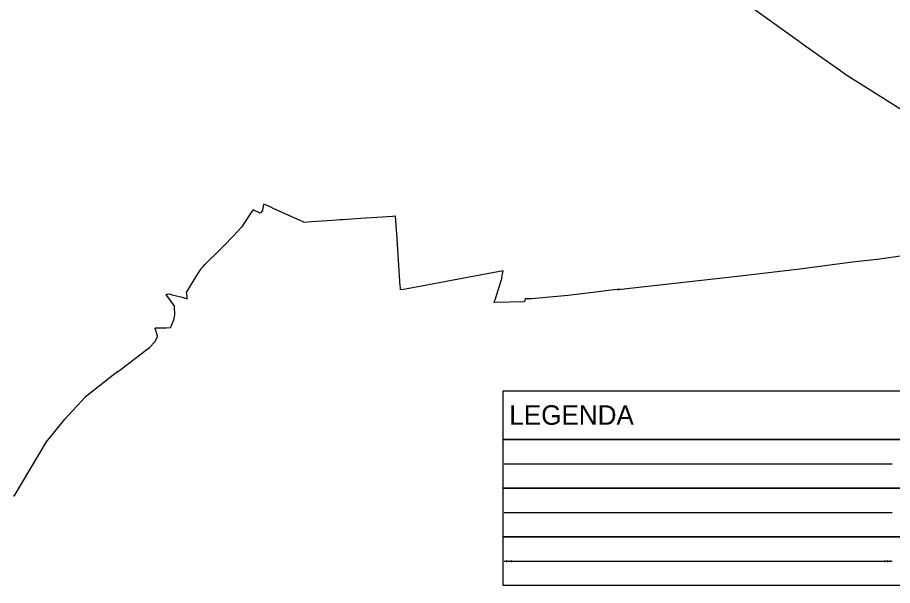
# Model space of a CAD drawing. Extents: x -601601 to -598591, y -1094361 to -1093021.
# Drawn here: x -600260 to -599362, y -1094361 to -1093778 of the extents above; entities that cross this region are included whole.
import ezdxf

# ---------------------------------------------------------------- set-up
doc = ezdxf.new("R2010")
doc.units = 0
for name, color, linetype in [('LEGENDA', 7, 'Continuous'), ('OVNE_PRE', 7, 'Continuous'), ('OVNE_SET', 7, 'Continuous')]:
    doc.layers.add(name, color=color, linetype=linetype)

msp = doc.modelspace()

# ---------------------------------------------------------------- linework, layer by layer
at = {"layer": 'LEGENDA'}
for p, q in [((-599760.54, -1094235.95), (-599362.54, -1094235.95)), ((-599760.54, -1094285.95), (-599362.54, -1094285.95)), ((-599760.54, -1094335.95), (-599362.54, -1094335.95))]:
    msp.add_line(p, q, dxfattribs=at)
for points in [[(-599761.54, -1094160.95), (-598861.54, -1094160.95), (-598861.54, -1094210.95), (-599761.54, -1094210.95), (-599761.54, -1094160.95)], [(-599761.54, -1094210.95), (-599361.54, -1094210.95), (-598861.54, -1094210.95), (-598861.54, -1094260.95), (-599361.54, -1094260.95), (-599761.54, -1094260.95), (-599761.54, -1094210.95)], [(-599761.54, -1094260.95), (-599361.54, -1094260.95), (-598861.54, -1094260.95), (-598861.54, -1094310.95), (-599361.54, -1094310.95), (-599761.54, -1094310.95), (-599761.54, -1094260.95)], [(-599761.54, -1094310.95), (-599361.54, -1094310.95), (-598861.54, -1094310.95), (-598861.54, -1094360.95), (-599361.54, -1094360.95), (-599761.54, -1094360.95), (-599761.54, -1094310.95)], [(-599758.21, -1094335.63), (-599758.02, -1094335.82), (-599758.02, -1094336.09), (-599758.21, -1094336.28), (-599758.48, -1094336.28), (-599758.67, -1094336.09), (-599758.67, -1094335.82), (-599758.48, -1094335.63), (-599758.21, -1094335.63), (-599758.2, -1094335.67), (-599758.44, -1094335.67), (-599758.52, -1094335.75), (-599758.12, -1094335.75), (-599758.06, -1094335.83), (-599758.6, -1094335.83), (-599758.6, -1094335.91), (-599758.07, -1094335.91), (-599758.06, -1094335.99), (-599758.59, -1094335.99), (-599758.59, -1094336.07), (-599758.06, -1094336.07), (-599758.11, -1094336.15), (-599758.54, -1094336.15), (-599758.47, -1094336.23), (-599758.19, -1094336.23)], [(-599755.7, -1094335.63), (-599755.51, -1094335.82), (-599755.51, -1094336.09), (-599755.7, -1094336.28), (-599755.97, -1094336.28), (-599756.16, -1094336.09), (-599756.16, -1094335.82), (-599755.97, -1094335.63), (-599755.7, -1094335.63), (-599755.71, -1094335.67), (-599755.95, -1094335.67), (-599756.03, -1094335.75), (-599755.63, -1094335.75), (-599755.55, -1094335.83), (-599756.11, -1094335.83), (-599756.11, -1094335.91), (-599755.55, -1094335.91), (-599755.55, -1094335.99), (-599756.11, -1094335.99), (-599756.11, -1094336.07), (-599755.55, -1094336.07), (-599755.63, -1094336.15), (-599756.03, -1094336.15), (-599755.95, -1094336.23), (-599755.71, -1094336.23)], [(-599753.19, -1094335.63), (-599753, -1094335.82), (-599753, -1094336.09), (-599753.19, -1094336.28), (-599753.46, -1094336.28), (-599753.65, -1094336.09), (-599753.65, -1094335.82), (-599753.46, -1094335.63), (-599753.19, -1094335.63), (-599753.23, -1094335.67), (-599753.47, -1094335.67), (-599753.53, -1094335.75), (-599753.15, -1094335.75), (-599753.07, -1094335.83), (-599753.59, -1094335.83), (-599753.59, -1094335.91), (-599753.07, -1094335.91), (-599753.07, -1094335.99), (-599753.59, -1094335.99), (-599753.6, -1094336.07), (-599753.08, -1094336.07), (-599753.12, -1094336.15), (-599753.53, -1094336.15), (-599753.48, -1094336.23), (-599753.24, -1094336.23)], [(-599369.61, -1094335.63), (-599369.42, -1094335.82), (-599369.42, -1094336.09), (-599369.61, -1094336.28), (-599369.88, -1094336.28), (-599370.07, -1094336.09), (-599370.07, -1094335.82), (-599369.88, -1094335.63), (-599369.61, -1094335.63), (-599369.6, -1094335.67), (-599369.84, -1094335.67), (-599369.92, -1094335.75), (-599369.52, -1094335.75), (-599369.46, -1094335.83), (-599370, -1094335.83), (-599370, -1094335.91), (-599369.47, -1094335.91), (-599369.46, -1094335.99), (-599369.99, -1094335.99), (-599369.99, -1094336.07), (-599369.46, -1094336.07), (-599369.51, -1094336.15), (-599369.94, -1094336.15), (-599369.87, -1094336.23), (-599369.59, -1094336.23)], [(-599367.1, -1094335.63), (-599366.91, -1094335.82), (-599366.91, -1094336.09), (-599367.1, -1094336.28), (-599367.37, -1094336.28), (-599367.56, -1094336.09), (-599367.56, -1094335.82), (-599367.37, -1094335.63), (-599367.1, -1094335.63), (-599367.11, -1094335.67), (-599367.35, -1094335.67), (-599367.43, -1094335.75), (-599367.03, -1094335.75), (-599366.95, -1094335.83), (-599367.51, -1094335.83), (-599367.51, -1094335.91), (-599366.95, -1094335.91), (-599366.95, -1094335.99), (-599367.51, -1094335.99), (-599367.51, -1094336.07), (-599366.95, -1094336.07), (-599367.03, -1094336.15), (-599367.43, -1094336.15), (-599367.35, -1094336.23), (-599367.11, -1094336.23)], [(-599364.59, -1094335.63), (-599364.4, -1094335.82), (-599364.4, -1094336.09), (-599364.59, -1094336.28), (-599364.86, -1094336.28), (-599365.05, -1094336.09), (-599365.05, -1094335.82), (-599364.86, -1094335.63), (-599364.59, -1094335.63), (-599364.63, -1094335.67), (-599364.87, -1094335.67), (-599364.93, -1094335.75), (-599364.55, -1094335.75), (-599364.47, -1094335.83), (-599364.99, -1094335.83), (-599364.99, -1094335.91), (-599364.47, -1094335.91), (-599364.47, -1094335.99), (-599364.99, -1094335.99), (-599365, -1094336.07), (-599364.48, -1094336.07), (-599364.52, -1094336.15), (-599364.93, -1094336.15), (-599364.88, -1094336.23), (-599364.64, -1094336.23)]]:
    msp.add_lwpolyline(points, dxfattribs=at)
at = {"layer": 'OVNE_PRE'}
for p, q in [((-600038.72, -1094002.43), (-600048.53, -1094012.25)), ((-600072.19, -1094035.93), (-600070.1, -1094033.84)), ((-599867.58, -1094055.18), (-599867.43, -1094057.3)), ((-599864.1, -1094057.18), (-599867.43, -1094057.3)), ((-600107.78, -1094062.54), (-600105.41, -1094061.56)), ((-600091.23, -1094064.88), (-600085.89, -1094066.6)), ((-600211.77, -1094190.11), (-600190.79, -1094167.75)), ((-600230.33, -1094213.3), (-600211.77, -1094190.11))]:
    msp.add_line(p, q, dxfattribs=at)
for points in [[(-599685.26, -1093704.64), (-599651.21, -1093708.18), (-599652.61, -1093713.7), (-599587.95, -1093722.56), (-599580.83, -1093723.54), (-599554.11, -1093735.19), (-599513.89, -1093762.08), (-599457.52, -1093802.56), (-599455.66, -1093803.88), (-599437.9, -1093816.49), (-599416.55, -1093831.64), (-599409.9, -1093836.36), (-599352.71, -1093872.39), (-599306.11, -1093901.75), (-599280.92, -1093914.77), (-599249.01, -1093931.27), (-599149.05, -1093964.07), (-599127.58, -1093974.03), (-599101.87, -1093988.24)], [(-599966.31, -1093987.84), (-599982.34, -1093980.76), (-599992.35, -1093976.35), (-599996.95, -1093974.38), (-600000, -1093972.7), (-600002.27, -1093971.68), (-600007.46, -1093969.37), (-600007.92, -1093971.37), (-600008.59, -1093976.08), (-600011.03, -1093978.59), (-600018.41, -1093975.42), (-600020.59, -1093978.44), (-600027.67, -1093988.82), (-600030.06, -1093992.92), (-600038.72, -1094002.43)], [(-599966.31, -1093987.84), (-599958.56, -1093987.32), (-599947.73, -1093986.59), (-599936.89, -1093985.85), (-599929.37, -1093985.34), (-599926.27, -1093985.12), (-599922.31, -1093984.86), (-599907.92, -1093983.88), (-599891.53, -1093982.77), (-599875.13, -1093981.65), (-599872.58, -1093981.48), (-599872.23, -1093986.62), (-599871.6, -1093995.88), (-599871.32, -1094000), (-599869.5, -1094026.84), (-599867.68, -1094053.67), (-599867.58, -1094055.18)], [(-599330.69, -1094019.58), (-599374.89, -1094025.84), (-599403.21, -1094029.14), (-599457.33, -1094036.05), (-599524.39, -1094044.13), (-599631.73, -1094056.02), (-599640.59, -1094056.95), (-599643.88, -1094057.26), (-599641.8, -1094056.68), (-599653.67, -1094058.18), (-599666.85, -1094059.85), (-599694.83, -1094063.4), (-599732.63, -1094066.54), (-599735.1, -1094066.77), (-599739.07, -1094066.83), (-599739.67, -1094069.86)], [(-599762.99, -1094044.48), (-599761.53, -1094037.94), (-599820.27, -1094048.89), (-599841.83, -1094052.91), (-599864.1, -1094057.18)], [(-599762.99, -1094044.48), (-599763.83, -1094047.18), (-599770.33, -1094068.13)], [(-600107.78, -1094062.54), (-600105.32, -1094065.97), (-600099.07, -1094074.69)], [(-600103.09, -1094096.54), (-600099.89, -1094088.32), (-600098.79, -1094082.98), (-600099.07, -1094074.69)], [(-600124.73, -1094116.46), (-600119.24, -1094110.69), (-600117.01, -1094106.19), (-600116.56, -1094104.88), (-600118.93, -1094096.93)], [(-600157.69, -1094141.49), (-600153.82, -1094138.8), (-600128.69, -1094119.63), (-600124.73, -1094116.46)]]:
    msp.add_lwpolyline(points, dxfattribs=at)
at = {"layer": 'OVNE_SET'}
for p, q in [((-600052.24, -1094015.96), (-600067.76, -1094031.49)), ((-600052.24, -1094015.96), (-600048.53, -1094012.25)), ((-600070.1, -1094033.84), (-600067.76, -1094031.49)), ((-600086.88, -1094059.45), (-600086.88, -1094059.45)), ((-599770.88, -1094070.57), (-599770.33, -1094068.13)), ((-599739.67, -1094069.86), (-599770.88, -1094070.57)), ((-599739.67, -1094069.86), (-599739.67, -1094069.86))]:
    msp.add_line(p, q, dxfattribs=at)
for points in [[(-600072.19, -1094035.93), (-600075.29, -1094040.9), (-600086.88, -1094059.45)], [(-600085.89, -1094066.6), (-600086.19, -1094064.43), (-600086.88, -1094059.45)], [(-600105.41, -1094061.56), (-600103.56, -1094061.99), (-600101.57, -1094062.46), (-600091.23, -1094064.88)], [(-600103.09, -1094096.54), (-600107.44, -1094096.65), (-600110.62, -1094096.73), (-600114.79, -1094096.83), (-600118.93, -1094096.93)], [(-600157.69, -1094141.49), (-600160.38, -1094143.5), (-600190.79, -1094167.75)], [(-600264.22, -1094268.41), (-600263.58, -1094269.34), (-600230.33, -1094213.3)]]:
    msp.add_lwpolyline(points, dxfattribs=at)

# ---------------------------------------------------------------- texts
at = {"layer": 'LEGENDA'}
msp.add_text('LEGENDA', height=20, dxfattribs=at).set_placement((-599755.34, -1094195.95))

doc.saveas('drawing.dxf')
